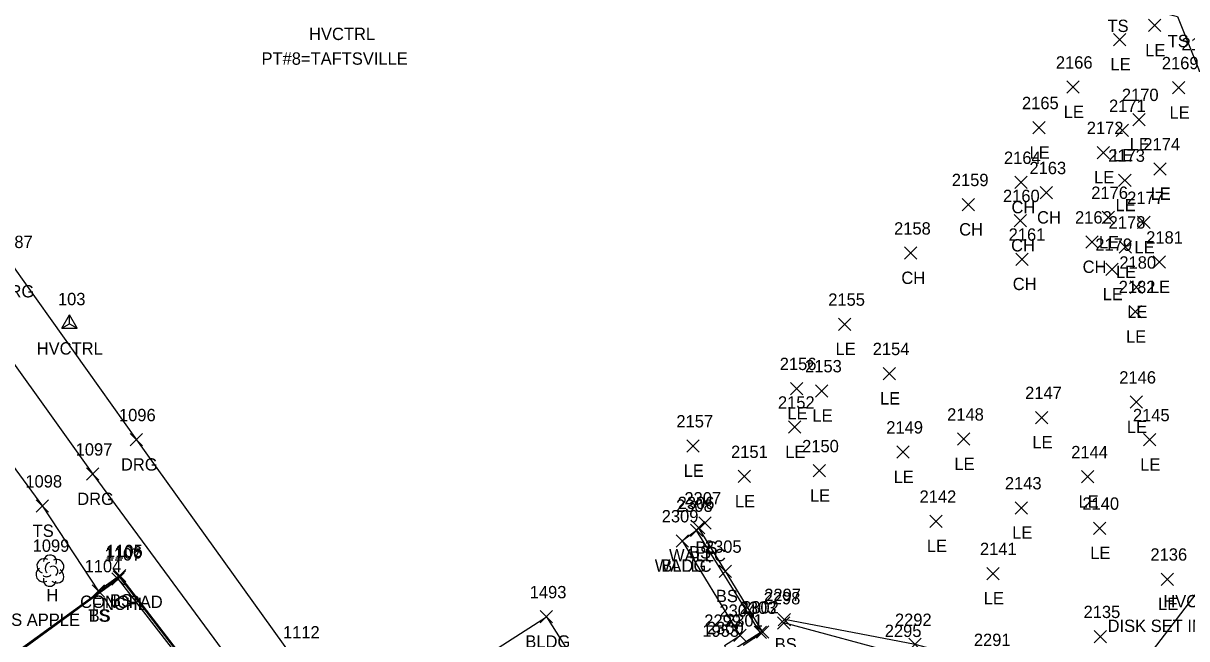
# Model space of a CAD drawing. Extents: x 1647133 to 1649138, y 411736 to 414924.
# Drawn here: x 1648689 to 1648877.6, y 412175.6 to 412275.3 of the extents above; entities that cross this region are included whole.
import ezdxf

# ---------------------------------------------------------------- set-up
doc = ezdxf.new("R2010")
doc.units = 0
for name, color, linetype in [('C_A', 7, 'Continuous'), ('C_C', 7, 'Continuous'), ('C_I', 7, 'Continuous'), ('CPSM', 7, 'Continuous'), ('L_A', 7, 'Continuous'), ('L_C', 7, 'Continuous'), ('L_I', 7, 'Continuous'), ('L_TIC', 7, 'Continuous'), ('LBC', 7, 'Continuous'), ('LELB', 7, 'Continuous'), ('LFNC', 7, 'Continuous'), ('LS', 7, 'Continuous'), ('LTD', 7, 'Continuous'), ('LW', 7, 'Continuous'), ('R_A', 7, 'Continuous'), ('R_I', 7, 'Continuous'), ('R_TIC', 7, 'Continuous'), ('RDG', 7, 'Continuous')]:
    doc.layers.add(name, color=color, linetype=linetype)

msp = doc.modelspace()

# ---------------------------------------------------------------- linework, layer by layer
at = {"layer": 'CPSM'}
for p, q in [((1648695.26, 412225.9), (1648696.51, 412228.06)), ((1648695.26, 412225.9), (1648696.51, 412226.62)), ((1648697.76, 412225.9), (1648696.51, 412228.06)), ((1648696.51, 412226.62), (1648696.51, 412228.06)), ((1648696.51, 412226.62), (1648696.51, 412226.62)), ((1648696.51, 412226.62), (1648697.76, 412225.9)), ((1648695.26, 412225.9), (1648697.76, 412225.9))]:
    msp.add_line(p, q, dxfattribs=at)
at = {"layer": 'L_TIC'}
for points in [[(1648871.37, 412273.96), (1648873.37, 412275.96)], [(1648873.37, 412273.96), (1648871.37, 412275.96)], [(1648865.73, 412271.66), (1648867.73, 412273.66)], [(1648867.73, 412271.66), (1648865.73, 412273.66)], [(1648858.16, 412263.95), (1648860.16, 412265.95)], [(1648860.16, 412263.95), (1648858.16, 412265.95)], [(1648875.3, 412263.85), (1648877.3, 412265.85)], [(1648877.3, 412263.85), (1648875.3, 412265.85)], [(1648868.85, 412258.7), (1648870.85, 412260.7)], [(1648870.85, 412258.7), (1648868.85, 412260.7)], [(1648852.62, 412257.38), (1648854.62, 412259.38)], [(1648854.62, 412257.38), (1648852.62, 412259.38)], [(1648866.12, 412256.93), (1648868.12, 412258.93)], [(1648868.12, 412256.93), (1648866.12, 412258.93)], [(1648863.07, 412253.35), (1648865.07, 412255.35)], [(1648865.07, 412253.35), (1648863.07, 412255.35)], [(1648872.25, 412250.69), (1648874.25, 412252.69)], [(1648874.25, 412250.69), (1648872.25, 412252.69)], [(1648849.7, 412248.51), (1648851.7, 412250.51)], [(1648851.7, 412248.51), (1648849.7, 412250.51)], [(1648866.55, 412248.85), (1648868.55, 412250.85)], [(1648868.55, 412248.85), (1648866.55, 412250.85)], [(1648853.83, 412246.85), (1648855.83, 412248.85)], [(1648855.83, 412246.85), (1648853.83, 412248.85)], [(1648841.21, 412244.91), (1648843.21, 412246.91)], [(1648843.21, 412244.91), (1648841.21, 412246.91)], [(1648849.63, 412242.33), (1648851.63, 412244.33)], [(1648851.63, 412242.33), (1648849.63, 412244.33)], [(1648863.86, 412242.84), (1648865.86, 412244.84)], [(1648865.86, 412242.84), (1648863.86, 412244.84)], [(1648869.63, 412242.03), (1648871.63, 412244.03)], [(1648871.63, 412242.03), (1648869.63, 412244.03)], [(1648861.22, 412238.85), (1648863.22, 412240.85)], [(1648863.22, 412238.85), (1648861.22, 412240.85)], [(1648866.63, 412238.04), (1648868.63, 412240.04)], [(1648868.63, 412238.04), (1648866.63, 412240.04)], [(1648831.84, 412237.06), (1648833.84, 412239.06)], [(1648833.84, 412237.06), (1648831.84, 412239.06)], [(1648849.9, 412236.07), (1648851.9, 412238.07)], [(1648851.9, 412236.07), (1648849.9, 412238.07)], [(1648864.47, 412234.43), (1648866.47, 412236.43)], [(1648866.47, 412234.43), (1648864.47, 412236.43)], [(1648872.14, 412235.6), (1648874.14, 412237.6)], [(1648874.14, 412235.6), (1648872.14, 412237.6)], [(1648868.44, 412231.54), (1648870.44, 412233.54)], [(1648870.44, 412231.54), (1648868.44, 412233.54)], [(1648868.25, 412227.57), (1648870.25, 412229.57)], [(1648870.25, 412227.57), (1648868.25, 412229.57)], [(1648821.17, 412225.53), (1648823.17, 412227.53)], [(1648823.17, 412225.53), (1648821.17, 412227.53)], [(1648828.38, 412217.53), (1648830.38, 412219.53)], [(1648830.38, 412217.53), (1648828.38, 412219.53)], [(1648813.37, 412215.11), (1648815.37, 412217.11)], [(1648815.37, 412215.11), (1648813.37, 412217.11)], [(1648817.42, 412214.74), (1648819.42, 412216.74)], [(1648819.42, 412214.74), (1648817.42, 412216.74)], [(1648868.39, 412212.92), (1648870.39, 412214.92)], [(1648870.39, 412212.92), (1648868.39, 412214.92)], [(1648853.08, 412210.42), (1648855.08, 412212.42)], [(1648855.08, 412210.42), (1648853.08, 412212.42)], [(1648813.03, 412208.86), (1648815.03, 412210.86)], [(1648815.03, 412208.86), (1648813.03, 412210.86)], [(1648796.56, 412205.81), (1648798.56, 412207.81)], [(1648798.56, 412205.81), (1648796.56, 412207.81)], [(1648840.44, 412206.92), (1648842.44, 412208.92)], [(1648842.44, 412206.92), (1648840.44, 412208.92)], [(1648870.55, 412206.82), (1648872.55, 412208.82)], [(1648872.55, 412206.82), (1648870.55, 412208.82)], [(1648830.59, 412204.83), (1648832.59, 412206.83)], [(1648832.59, 412204.83), (1648830.59, 412206.83)], [(1648817.03, 412201.79), (1648819.03, 412203.79)], [(1648819.03, 412201.79), (1648817.03, 412203.79)], [(1648804.86, 412200.87), (1648806.86, 412202.87)], [(1648806.86, 412200.87), (1648804.86, 412202.87)], [(1648860.55, 412200.82), (1648862.55, 412202.82)], [(1648862.55, 412200.82), (1648860.55, 412202.82)], [(1648691.13, 412196.08), (1648693.13, 412198.08)], [(1648693.13, 412196.08), (1648691.13, 412198.08)], [(1648849.8, 412195.78), (1648851.8, 412197.78)], [(1648851.8, 412195.78), (1648849.8, 412197.78)], [(1648797.47, 412192.59), (1648799.47, 412194.59)], [(1648799.47, 412192.59), (1648797.47, 412194.59)], [(1648798.51, 412193.34), (1648800.51, 412195.34)], [(1648800.51, 412193.34), (1648798.51, 412195.34)], [(1648835.97, 412193.61), (1648837.97, 412195.61)], [(1648837.97, 412193.61), (1648835.97, 412195.61)], [(1648862.45, 412192.48), (1648864.45, 412194.48)], [(1648864.45, 412192.48), (1648862.45, 412194.48)], [(1648794.84, 412190.43), (1648796.84, 412192.43)], [(1648796.84, 412190.43), (1648794.84, 412192.43)], [(1648794.84, 412190.43), (1648796.84, 412192.43)], [(1648796.84, 412190.43), (1648794.84, 412192.43)], [(1648797.15, 412192.14), (1648799.15, 412194.14)], [(1648799.15, 412192.14), (1648797.15, 412194.14)], [(1648703.64, 412184.8), (1648705.64, 412186.8)], [(1648705.64, 412184.8), (1648703.64, 412186.8)], [(1648801.83, 412185.51), (1648803.83, 412187.51)], [(1648803.83, 412185.51), (1648801.83, 412187.51)], [(1648845.19, 412185.14), (1648847.19, 412187.14)], [(1648847.19, 412185.14), (1648845.19, 412187.14)], [(1648703.39, 412184.25), (1648705.39, 412186.25)], [(1648705.39, 412184.25), (1648703.39, 412186.25)], [(1648703.59, 412184.57), (1648705.59, 412186.57)], [(1648705.59, 412184.57), (1648703.59, 412186.57)], [(1648873.45, 412184.23), (1648875.45, 412186.23)], [(1648875.45, 412184.23), (1648873.45, 412186.23)], [(1648700.17, 412182.34), (1648702.17, 412184.34)], [(1648702.17, 412182.34), (1648700.17, 412184.34)], [(1648700.17, 412182.34), (1648702.17, 412184.34)], [(1648702.17, 412182.34), (1648700.17, 412184.34)], [(1648772.8, 412178.13), (1648774.8, 412180.13)], [(1648774.8, 412178.13), (1648772.8, 412180.13)], [(1648811.37, 412177.69), (1648813.37, 412179.69)], [(1648813.37, 412177.69), (1648811.37, 412179.69)], [(1648807.47, 412175.6), (1648809.47, 412177.6)], [(1648809.47, 412175.6), (1648807.47, 412177.6)], [(1648807.86, 412175.67), (1648809.86, 412177.67)], [(1648809.86, 412175.67), (1648807.86, 412177.67)], [(1648811.27, 412177.15), (1648813.27, 412179.15)], [(1648813.27, 412177.15), (1648811.27, 412179.15)], [(1648804.19, 412175.13), (1648806.19, 412177.13)], [(1648806.19, 412175.13), (1648804.19, 412177.13)], [(1648832.55, 412173.65), (1648834.55, 412175.65)], [(1648834.55, 412173.65), (1648832.55, 412175.65)], [(1648862.56, 412174.93), (1648864.56, 412176.93)], [(1648864.56, 412174.93), (1648862.56, 412176.93)]]:
    msp.add_lwpolyline(points, dxfattribs=at)
at = {"layer": 'LBC'}
for points in [[(1648802.66, 412174.51), (1648805.19, 412176.13), (1648795.84, 412191.43)], [(1648756.49, 412168.26), (1648756.98, 412168.33), (1648773.8, 412179.13), (1648784.12, 412162.76), (1648787.39, 412164.77), (1648787.88, 412165.38)]]:
    msp.add_lwpolyline(points, dxfattribs=at)
at = {"layer": 'LELB'}
for points in [[(1648866.33, 412278.88), (1648876.09, 412276.42), (1648879.49, 412267.93), (1648882.68, 412258.79), (1648883.57, 412248.77), (1648885.15, 412240.42), (1648883.59, 412228.33), (1648886.6, 412217.63), (1648887.94, 412203.28), (1648883.63, 412188.87), (1648865.63, 412165.29), (1648858.29, 412164.92), (1648847.42, 412160.58)], [(1648676.01, 412218.97), (1648692.13, 412197.08), (1648701.17, 412183.34)], [(1648805.69, 412174.56), (1648808.86, 412176.67), (1648802.83, 412186.51), (1648798.47, 412193.59), (1648799.51, 412194.34)], [(1648701.17, 412183.34), (1648704.64, 412185.8), (1648720.8, 412164.77), (1648740.45, 412139.27), (1648738.84, 412137.95), (1648750.19, 412122.59)], [(1648847.42, 412160.58), (1648847.92, 412167.89), (1648845.78, 412171.4), (1648833.55, 412174.65), (1648812.37, 412178.69)]]:
    msp.add_lwpolyline(points, dxfattribs=at)
at = {"layer": 'LFNC'}
msp.add_lwpolyline([(1648684.27, 412170.55), (1648704.39, 412185.25), (1648720.46, 412164.52), (1648739.79, 412139.41), (1648738.28, 412138.06), (1648736.27, 412136.35), (1648725.23, 412127.52), (1648716.27, 412129.58)], dxfattribs=at)
at = {"layer": 'LS'}
msp.add_lwpolyline([(1648683.77, 412170.47), (1648704.59, 412185.57), (1648720.68, 412164.75), (1648740.21, 412139.35), (1648738.37, 412137.97), (1648738.28, 412138.06)], dxfattribs=at)
at = {"layer": 'LTD'}
msp.add_line((1648693.32, 412186.66), (1648693.32, 412186.66), dxfattribs=at)
msp.add_line((1648693.32, 412186.66), (1648693.32, 412186.66), dxfattribs=at)
msp.add_arc((1648693.37, 412188.1), 1.05, 335.5272, 180.9563, dxfattribs=at)
for centre, major_axis, ratio, start_param, end_param in [((1648692.53, 412187.33), (1.21, -0.51), 0.895232, 1.570796, 4.712389), ((1648692.24, 412185.96), (0.58, -1.04), 0.959034, 3.141593, 6.283185), ((1648693.11, 412187.12), (-0.208, -0.792), 0.645439, 3.141593, 6.283185), ((1648693.82, 412186.5), (-0.5, 0.667), 0.989748, 3.141593, 6.283185), ((1648694.36, 412187.25), (-1.14, -0.48), 0.949671, 1.570796, 4.712389), ((1648693.32, 412185.16), (0.26, 1.06), 0.942809, 1.570796, 4.712389), ((1648692.86, 412185.91), (-0.625, -0.083), 0.423636, 0, 3.141593), ((1648694.32, 412185.83), (-1.09, 0.79), 0.841452, 1.570796, 4.712389)]:
    msp.add_ellipse(centre, major_axis=major_axis, ratio=ratio, start_param=start_param, end_param=end_param, dxfattribs=at)
at = {"layer": 'LW'}
for points in [[(1648802.66, 412174.51), (1648803.24, 412173.32), (1648808.47, 412176.6), (1648798.15, 412193.14), (1648795.84, 412191.43)], [(1648842.52, 412160.66), (1648845.05, 412169.81), (1648831.9, 412172.86), (1648812.27, 412178.15)]]:
    msp.add_lwpolyline(points, dxfattribs=at)
at = {"layer": 'R_TIC'}
for points in [[(1648706.36, 412206.82), (1648708.36, 412208.82)], [(1648708.36, 412206.82), (1648706.36, 412208.82)], [(1648699.28, 412201.25), (1648701.28, 412203.25)], [(1648701.28, 412201.25), (1648699.28, 412203.25)]]:
    msp.add_lwpolyline(points, dxfattribs=at)
at = {"layer": 'RDG'}
for points in [[(1648665.44, 412272.8), (1648687.37, 412235.88), (1648707.36, 412207.82), (1648732.67, 412172.62), (1648752.06, 412147.32), (1648777.8, 412111.4), (1648801.74, 412083.08)], [(1648657.18, 412267.78), (1648679.81, 412230.81), (1648700.28, 412202.25), (1648725.64, 412167.85), (1648744.33, 412141.94), (1648771.48, 412106.33), (1648789.56, 412080), (1648790.94, 412077.17)]]:
    msp.add_lwpolyline(points, dxfattribs=at)

# ---------------------------------------------------------------- texts
at = {"layer": 'C_A'}
for p in [(1648735.34, 412272.58), (1648691.2, 412221.62), (1648873.79, 412180.67)]:
    msp.add_text('HVCTRL', height=2, dxfattribs=at).set_placement(p)
at = {"layer": 'C_C'}
for s, p in [('PT#8=TAFTSVILLE', (1648727.63, 412268.58)), ('DISK SET IN LEDGE', (1648864.76, 412176.67))]:
    msp.add_text(s, height=2, dxfattribs=at).set_placement(p)
at = {"layer": 'C_I'}
msp.add_text('103', height=2, dxfattribs=at).set_placement((1648694.64, 412229.62))
at = {"layer": 'L_A'}
for s, p in [('TS', (1648864.74, 412273.88)), ('LE', (1648870.85, 412269.96)), ('TS', (1648874.5, 412271.42)), ('LE', (1648865.22, 412267.66)), ('LE', (1648857.65, 412259.95)), ('LE', (1648874.79, 412259.85)), ('LE', (1648868.34, 412254.7)), ('LE', (1648852.11, 412253.38)), ('LE', (1648865.61, 412252.93)), ('LE', (1648862.56, 412249.35)), ('LE', (1648871.73, 412246.69)), ('CH', (1648849.18, 412244.51)), ('LE', (1648866.04, 412244.85)), ('CH', (1648853.32, 412242.85)), ('CH', (1648840.7, 412240.91)), ('CH', (1648849.12, 412238.33)), ('LE', (1648863.35, 412238.84)), ('LE', (1648869.11, 412238.03)), ('CH', (1648860.71, 412234.85)), ('LE', (1648866.11, 412234.04)), ('CH', (1648831.33, 412233.06)), ('CH', (1648849.38, 412232.07)), ('LE', (1648863.96, 412230.43)), ('LE', (1648871.62, 412231.6)), ('LE', (1648867.93, 412227.54)), ('LE', (1648867.74, 412223.57)), ('LE', (1648820.66, 412221.53)), ('LE', (1648827.87, 412213.53)), ('LE', (1648812.86, 412211.11)), ('LE', (1648816.91, 412210.74)), ('LE', (1648867.88, 412208.92)), ('LE', (1648852.57, 412206.42)), ('LE', (1648812.51, 412204.86)), ('LE', (1648796.05, 412201.81)), ('LE', (1648839.93, 412202.92)), ('LE', (1648870.04, 412202.82)), ('LE', (1648830.08, 412200.83)), ('LE', (1648804.35, 412196.87)), ('LE', (1648816.52, 412197.79)), ('LE', (1648860.04, 412196.82)), ('TS', (1648690.54, 412192.08)), ('LE', (1648849.29, 412191.78)), ('BS', (1648796.91, 412188.59)), ('BS', (1648797.95, 412189.34)), ('LE', (1648835.46, 412189.61)), ('WALLC', (1648793.68, 412188.14)), ('LE', (1648861.94, 412188.48)), ('WALLC', (1648791.37, 412186.43)), ('BLDG', (1648792.43, 412186.43)), ('H', (1648692.76, 412181.66)), ('BS', (1648801.27, 412181.51)), ('LE', (1648844.68, 412181.14)), ('CONCPAD', (1648698.24, 412180.57)), ('FNCHL', (1648700.14, 412180.25)), ('BS', (1648703.08, 412180.8)), ('LE', (1648872.93, 412180.23)), ('TS', (1648699.58, 412178.34)), ('BS', (1648699.61, 412178.34)), ('BLDG', (1648770.39, 412174.13)), ('BS', (1648810.81, 412173.69))]:
    msp.add_text(s, height=2, dxfattribs=at).set_placement(p)
at = {"layer": 'L_C'}
msp.add_text('S APPLE', height=2, dxfattribs=at).set_placement((1648687.06, 412177.66))
at = {"layer": 'L_I'}
for s, p in [('2126', (1648876.74, 412270.93)), ('2166', (1648856.37, 412267.95)), ('2169', (1648873.55, 412267.85)), ('2170', (1648867.07, 412262.7)), ('2165', (1648850.88, 412261.38)), ('2171', (1648864.99, 412260.93)), ('2172', (1648861.38, 412257.35)), ('2174', (1648870.55, 412254.69)), ('2173', (1648864.86, 412252.85)), ('2164', (1648847.96, 412252.51)), ('2163', (1648852.09, 412250.85)), ('2159', (1648839.51, 412248.91)), ('2160', (1648847.8, 412246.33)), ('2176', (1648862.11, 412246.84)), ('2177', (1648867.93, 412246.03)), ('2162', (1648859.48, 412242.85)), ('2178', (1648864.93, 412242.04)), ('2158', (1648830.15, 412241.06)), ('2161', (1648848.72, 412240.07)), ('2181', (1648871.01, 412239.6)), ('2179', (1648862.77, 412238.43)), ('2180', (1648866.66, 412235.54)), ('2182', (1648866.56, 412231.57)), ('2155', (1648819.48, 412229.53)), ('2154', (1648826.69, 412221.53)), ('2156', (1648811.62, 412219.11)), ('2153', (1648815.73, 412218.74)), ('2146', (1648866.65, 412216.92)), ('2147', (1648851.39, 412214.42)), ('2152', (1648811.33, 412212.86)), ('2157', (1648794.87, 412209.81)), ('2148', (1648838.75, 412210.92)), ('2145', (1648868.86, 412210.82)), ('2149', (1648828.89, 412208.83)), ('2150', (1648815.25, 412205.79)), ('2151', (1648803.73, 412204.87)), ('2144', (1648858.86, 412204.82)), ('1098', (1648689.36, 412200.08)), ('2143', (1648848.11, 412199.78)), ('2308', (1648794.81, 412196.14)), ('2306', (1648795.08, 412196.59)), ('2307', (1648796.17, 412197.34)), ('2142', (1648834.28, 412197.61)), ('2140', (1648860.67, 412196.48)), ('2309', (1648792.49, 412194.43)), ('2309', (1648792.49, 412194.43)), ('1099', (1648690.54, 412189.66)), ('1106', (1648702.33, 412188.57)), ('1105', (1648702.44, 412188.8)), ('2305', (1648799.49, 412189.51)), ('2141', (1648844.07, 412189.14)), ('1107', (1648702.19, 412188.25)), ('2136', (1648871.7, 412188.23)), ('1104', (1648698.96, 412186.34)), ('1104', (1648698.96, 412186.34)), ('1493', (1648771.1, 412182.13)), ('2298', (1648809.01, 412181.15)), ('2297', (1648809.11, 412181.69)), ('2304', (1648801.85, 412179.13)), ('2303', (1648805.13, 412179.6)), ('2302', (1648805.52, 412179.67)), ('2299', (1648799.39, 412177.51)), ('2299', (1648799.39, 412177.51)), ('2301', (1648802.92, 412177.56)), ('2301', (1648802.92, 412177.56)), ('2292', (1648830.29, 412177.65)), ('2135', (1648860.86, 412178.93)), ('1953', (1648799.08, 412175.89)), ('2300', (1648799.82, 412176.32)), ('2295', (1648828.64, 412175.86)), ('2291', (1648843.08, 412174.4))]:
    msp.add_text(s, height=2, dxfattribs=at).set_placement(p)
at = {"layer": 'R_A'}
for p in [(1648684.86, 412230.88), (1648704.85, 412202.82), (1648697.77, 412197.25)]:
    msp.add_text('DRG', height=2, dxfattribs=at).set_placement(p)
at = {"layer": 'R_I'}
for s, p in [('1087', (1648684.6, 412238.88)), ('1096', (1648704.53, 412210.82)), ('1097', (1648697.51, 412205.25)), ('1112', (1648731.11, 412175.62))]:
    msp.add_text(s, height=2, dxfattribs=at).set_placement(p)

doc.saveas('drawing.dxf')
